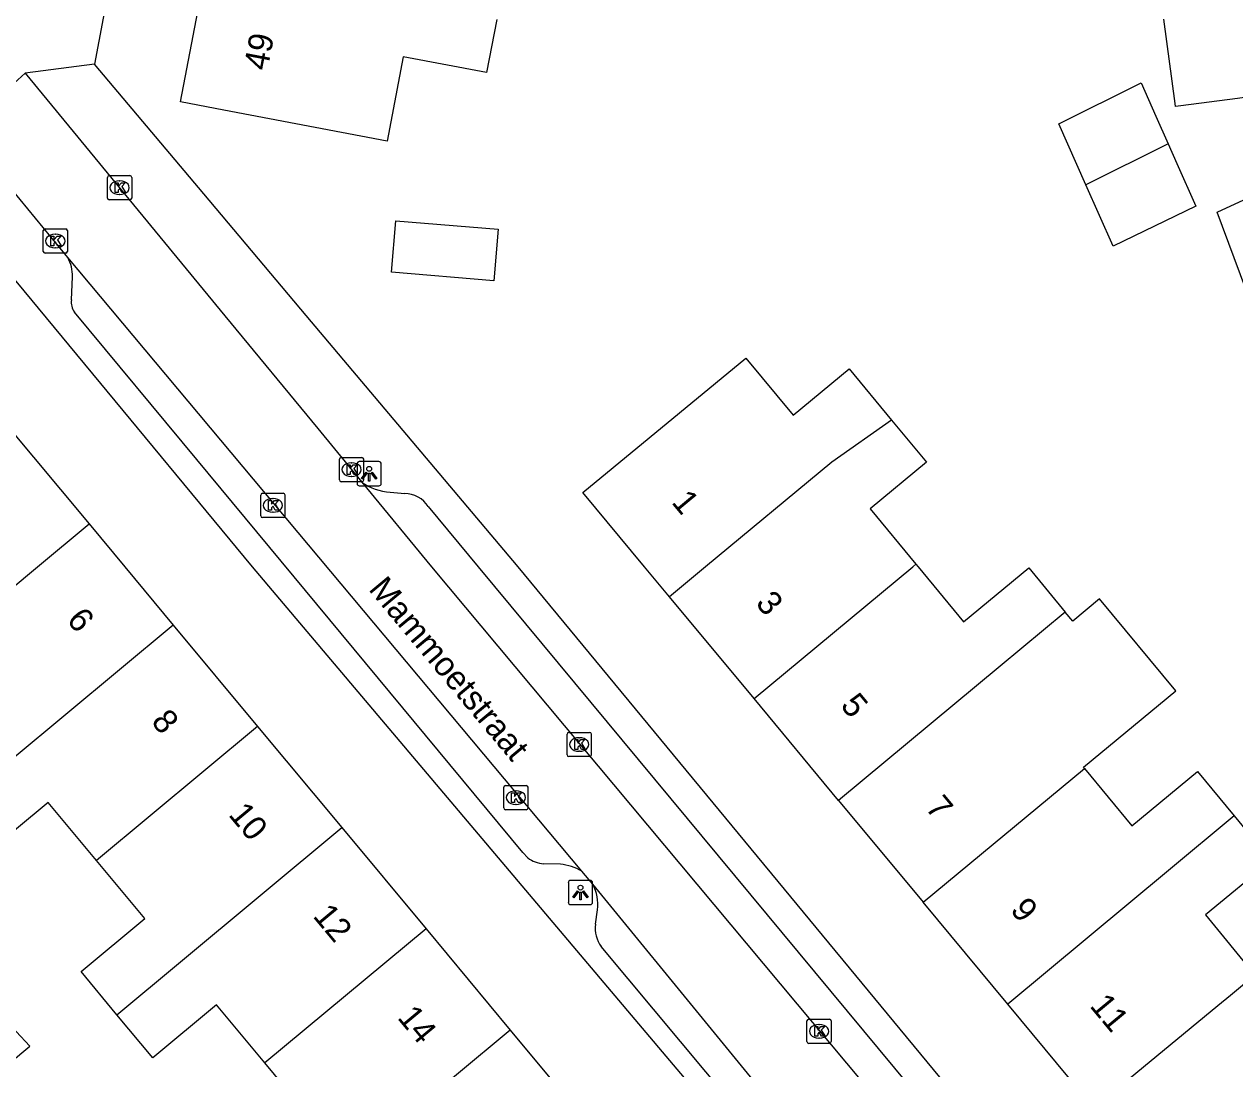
# Model space of a CAD drawing. Extents: x 163150 to 163546, y 380933 to 381635.
# Drawn here: x 163434.69 to 163484.57, y 380979.31 to 381022.35 of the extents above; entities that cross this region are included whole.
import ezdxf

# ---------------------------------------------------------------- set-up
doc = ezdxf.new("R2010")
doc.units = 0
for name, color, linetype in [('IMGEO_Kolk', 7, 'Continuous'), ('IMGEO_Lichtpunt', 7, 'Continuous'), ('IMGEO_Openbare_ruimte_label', 7, 'Continuous'), ('IMGEO_Pand', 7, 'Continuous'), ('IMGEO_Pand_nummerreeks', 7, 'Continuous'), ('IMGEO_Rijbaan_lokaal_open', 7, 'Continuous'), ('IMGEO_Voetpad_open', 7, 'Continuous')]:
    doc.layers.add(name, color=color, linetype=linetype)

msp = doc.modelspace()

# ---------------------------------------------------------------- linework, layer by layer
at = {"layer": 'IMGEO_Kolk'}
for p, q in [((163438.118, 381015.193), (163438.118, 381016.045)), ((163438.193, 381016.119), (163439.045, 381016.119)), ((163438.606, 381015.899), (163438.631, 381015.899)), ((163439.119, 381016.045), (163439.119, 381015.193)), ((163438.629, 381015.339), (163438.604, 381015.339)), ((163439.045, 381015.119), (163438.193, 381015.119)), ((163435.473, 381012.996), (163435.473, 381013.848)), ((163435.548, 381013.922), (163436.4, 381013.922)), ((163436.474, 381013.848), (163436.474, 381012.996)), ((163435.961, 381013.702), (163435.986, 381013.702)), ((163436.4, 381012.922), (163435.548, 381012.922)), ((163435.984, 381013.142), (163435.959, 381013.142)), ((163447.675, 381003.575), (163447.675, 381004.427)), ((163447.75, 381004.501), (163448.602, 381004.501)), ((163448.676, 381004.427), (163448.676, 381003.575)), ((163448.163, 381004.281), (163448.188, 381004.281)), ((163448.602, 381003.501), (163447.75, 381003.501)), ((163448.186, 381003.721), (163448.161, 381003.721)), ((163444.434, 381002.1), (163444.434, 381002.952)), ((163444.509, 381003.026), (163445.361, 381003.026)), ((163445.435, 381002.952), (163445.435, 381002.1)), ((163444.922, 381002.806), (163444.947, 381002.806)), ((163445.361, 381002.026), (163444.509, 381002.026)), ((163444.945, 381002.246), (163444.92, 381002.246)), ((163457.055, 380992.249), (163457.055, 380993.101)), ((163457.13, 380993.175), (163457.982, 380993.175)), ((163457.543, 380992.955), (163457.568, 380992.955)), ((163458.056, 380993.101), (163458.056, 380992.249)), ((163457.566, 380992.395), (163457.541, 380992.395)), ((163457.982, 380992.175), (163457.13, 380992.175)), ((163454.446, 380990.061), (163454.446, 380990.913)), ((163454.521, 380990.987), (163455.373, 380990.987)), ((163455.447, 380990.913), (163455.447, 380990.061)), ((163454.934, 380990.767), (163454.959, 380990.767)), ((163455.373, 380989.987), (163454.521, 380989.987)), ((163454.957, 380990.207), (163454.932, 380990.207)), ((163466.94, 380980.432), (163466.94, 380981.284)), ((163467.015, 380981.358), (163467.867, 380981.358)), ((163467.428, 380981.138), (163467.453, 380981.138)), ((163467.941, 380981.284), (163467.941, 380980.432)), ((163467.451, 380980.578), (163467.426, 380980.578)), ((163467.867, 380980.358), (163467.015, 380980.358))]:
    msp.add_line(p, q, dxfattribs=at)
for points in [[(163438.118, 381015.193), (163438.118, 381016.045)], [(163438.193, 381016.119), (163439.045, 381016.119)], [(163438.439, 381015.819), (163438.562, 381015.819), (163438.562, 381015.668), (163438.692, 381015.819), (163438.856, 381015.819), (163438.71, 381015.668), (163438.863, 381015.419), (163438.711, 381015.419), (163438.626, 381015.583), (163438.562, 381015.516), (163438.562, 381015.419), (163438.439, 381015.419), (163438.439, 381015.819)], [(163439.119, 381016.045), (163439.119, 381015.193)], [(163439.045, 381015.119), (163438.193, 381015.119)], [(163435.473, 381012.996), (163435.473, 381013.848)], [(163435.548, 381013.922), (163436.4, 381013.922)], [(163436.474, 381013.848), (163436.474, 381012.996)], [(163435.794, 381013.622), (163435.917, 381013.622), (163435.917, 381013.471), (163436.047, 381013.622), (163436.211, 381013.622), (163436.065, 381013.471), (163436.218, 381013.222), (163436.066, 381013.222), (163435.981, 381013.386), (163435.917, 381013.319), (163435.917, 381013.222), (163435.794, 381013.222), (163435.794, 381013.622)], [(163436.4, 381012.922), (163435.548, 381012.922)], [(163447.675, 381003.575), (163447.675, 381004.427)], [(163447.75, 381004.501), (163448.602, 381004.501)], [(163448.676, 381004.427), (163448.676, 381003.575)], [(163447.996, 381004.201), (163448.119, 381004.201), (163448.119, 381004.05), (163448.249, 381004.201), (163448.413, 381004.201), (163448.267, 381004.05), (163448.42, 381003.801), (163448.268, 381003.801), (163448.183, 381003.965), (163448.119, 381003.898), (163448.119, 381003.801), (163447.996, 381003.801), (163447.996, 381004.201)], [(163448.602, 381003.501), (163447.75, 381003.501)], [(163444.434, 381002.1), (163444.434, 381002.952)], [(163444.509, 381003.026), (163445.361, 381003.026)], [(163445.435, 381002.952), (163445.435, 381002.1)], [(163444.755, 381002.726), (163444.878, 381002.726), (163444.878, 381002.575), (163445.008, 381002.726), (163445.172, 381002.726), (163445.026, 381002.575), (163445.179, 381002.326), (163445.027, 381002.326), (163444.942, 381002.49), (163444.878, 381002.423), (163444.878, 381002.326), (163444.755, 381002.326), (163444.755, 381002.726)], [(163445.361, 381002.026), (163444.509, 381002.026)], [(163457.055, 380992.249), (163457.055, 380993.101)], [(163457.13, 380993.175), (163457.982, 380993.175)], [(163457.376, 380992.875), (163457.499, 380992.875), (163457.499, 380992.724), (163457.629, 380992.875), (163457.793, 380992.875), (163457.647, 380992.724), (163457.8, 380992.475), (163457.648, 380992.475), (163457.563, 380992.639), (163457.499, 380992.572), (163457.499, 380992.475), (163457.376, 380992.475), (163457.376, 380992.875)], [(163458.056, 380993.101), (163458.056, 380992.249)], [(163457.982, 380992.175), (163457.13, 380992.175)], [(163454.446, 380990.061), (163454.446, 380990.913)], [(163454.521, 380990.987), (163455.373, 380990.987)], [(163455.447, 380990.913), (163455.447, 380990.061)], [(163454.767, 380990.687), (163454.89, 380990.687), (163454.89, 380990.536), (163455.02, 380990.687), (163455.184, 380990.687), (163455.038, 380990.536), (163455.191, 380990.287), (163455.039, 380990.287), (163454.954, 380990.451), (163454.89, 380990.384), (163454.89, 380990.287), (163454.767, 380990.287), (163454.767, 380990.687)], [(163455.373, 380989.987), (163454.521, 380989.987)], [(163466.94, 380980.432), (163466.94, 380981.284)], [(163467.015, 380981.358), (163467.867, 380981.358)], [(163467.261, 380981.058), (163467.384, 380981.058), (163467.384, 380980.907), (163467.514, 380981.058), (163467.678, 380981.058), (163467.532, 380980.907), (163467.685, 380980.658), (163467.533, 380980.658), (163467.448, 380980.822), (163467.384, 380980.755), (163467.384, 380980.658), (163467.261, 380980.658), (163467.261, 380981.058)], [(163467.941, 380981.284), (163467.941, 380980.432)], [(163467.867, 380980.358), (163467.015, 380980.358)]]:
    msp.add_lwpolyline(points, dxfattribs=at)
for centre, start, end in [((163438.195, 381016.043), 91.552, 178.448), ((163438.195, 381016.043), 91.552, 178.448), ((163439.043, 381016.043), 1.552, 88.448), ((163439.043, 381016.043), 1.552, 88.448), ((163438.195, 381015.195), 181.552, 268.448), ((163438.195, 381015.195), 181.552, 268.448), ((163439.043, 381015.195), 271.552, 358.448), ((163439.043, 381015.195), 271.552, 358.448), ((163435.55, 381013.846), 91.552, 178.448), ((163435.55, 381013.846), 91.552, 178.448), ((163436.398, 381013.846), 1.552, 88.448), ((163436.398, 381013.846), 1.552, 88.448), ((163435.55, 381012.998), 181.552, 268.448), ((163435.55, 381012.998), 181.552, 268.448), ((163436.398, 381012.998), 271.552, 358.448), ((163436.398, 381012.998), 271.552, 358.448), ((163447.752, 381004.425), 91.552, 178.448), ((163447.752, 381004.425), 91.552, 178.448), ((163448.6, 381004.425), 1.552, 88.448), ((163448.6, 381004.425), 1.552, 88.448), ((163447.752, 381003.577), 181.552, 268.448), ((163447.752, 381003.577), 181.552, 268.448), ((163448.6, 381003.577), 271.552, 358.448), ((163448.6, 381003.577), 271.552, 358.448), ((163444.511, 381002.95), 91.552, 178.448), ((163444.511, 381002.95), 91.552, 178.448), ((163445.359, 381002.95), 1.552, 88.448), ((163445.359, 381002.95), 1.552, 88.448), ((163444.511, 381002.102), 181.552, 268.448), ((163444.511, 381002.102), 181.552, 268.448), ((163445.359, 381002.102), 271.552, 358.448), ((163445.359, 381002.102), 271.552, 358.448), ((163457.132, 380993.099), 91.552, 178.448), ((163457.132, 380993.099), 91.552, 178.448), ((163457.98, 380993.099), 1.552, 88.448), ((163457.98, 380993.099), 1.552, 88.448), ((163457.132, 380992.251), 181.552, 268.448), ((163457.132, 380992.251), 181.552, 268.448), ((163457.98, 380992.251), 271.552, 358.448), ((163457.98, 380992.251), 271.552, 358.448), ((163454.523, 380990.911), 91.552, 178.448), ((163454.523, 380990.911), 91.552, 178.448), ((163455.371, 380990.911), 1.552, 88.448), ((163455.371, 380990.911), 1.552, 88.448), ((163454.523, 380990.063), 181.552, 268.448), ((163454.523, 380990.063), 181.552, 268.448), ((163455.371, 380990.063), 271.552, 358.448), ((163455.371, 380990.063), 271.552, 358.448), ((163467.017, 380981.282), 91.552, 178.448), ((163467.017, 380981.282), 91.552, 178.448), ((163467.865, 380981.282), 1.552, 88.448), ((163467.865, 380981.282), 1.552, 88.448), ((163467.017, 380980.434), 181.552, 268.448), ((163467.017, 380980.434), 181.552, 268.448), ((163467.865, 380980.434), 271.552, 358.448), ((163467.865, 380980.434), 271.552, 358.448)]:
    msp.add_arc(centre, 0.0765, start, end, dxfattribs=at)
for centre, major_axis, ratio, start_param, end_param in [((163438.605, 381015.619), (-0.387, 0.002), 0.722429, 4.712389, 7.853982), ((163438.63, 381015.619), (-0.39, 0.002), 0.717154, 1.570796, 4.712389), ((163435.96, 381013.422), (-0.387, 0.002), 0.722429, 4.712389, 7.853982), ((163435.985, 381013.422), (-0.39, 0.002), 0.717154, 1.570796, 4.712389), ((163448.162, 381004.001), (-0.387, 0.002), 0.722429, 4.712389, 7.853982), ((163448.187, 381004.001), (-0.39, 0.002), 0.717154, 1.570796, 4.712389), ((163444.921, 381002.526), (-0.387, 0.002), 0.722429, 4.712389, 7.853982), ((163444.946, 381002.526), (-0.39, 0.002), 0.717154, 1.570796, 4.712389), ((163457.542, 380992.675), (-0.387, 0.002), 0.722429, 4.712389, 7.853982), ((163457.567, 380992.675), (-0.39, 0.002), 0.717154, 1.570796, 4.712389), ((163454.933, 380990.487), (-0.387, 0.002), 0.722429, 4.712389, 7.853982), ((163454.958, 380990.487), (-0.39, 0.002), 0.717154, 1.570796, 4.712389), ((163467.427, 380980.858), (-0.387, 0.002), 0.722429, 4.712389, 7.853982), ((163467.452, 380980.858), (-0.39, 0.002), 0.717154, 1.570796, 4.712389)]:
    msp.add_ellipse(centre, major_axis=major_axis, ratio=ratio, start_param=start_param, end_param=end_param, dxfattribs=at)
at = {"layer": 'IMGEO_Lichtpunt'}
for p, q in [((163449.305, 381004.332), (163448.497, 381004.332)), ((163449.305, 381004.332), (163448.497, 381004.332)), ((163448.403, 381004.237), (163448.403, 381003.43)), ((163448.403, 381004.237), (163448.403, 381003.43)), ((163449.399, 381003.43), (163449.399, 381004.237)), ((163449.399, 381003.43), (163449.399, 381004.237)), ((163448.497, 381003.336), (163449.305, 381003.336)), ((163448.497, 381003.336), (163449.305, 381003.336)), ((163457.109, 380986.981), (163457.109, 380986.174)), ((163457.109, 380986.981), (163457.109, 380986.174)), ((163458.011, 380987.076), (163457.203, 380987.076)), ((163458.011, 380987.076), (163457.203, 380987.076)), ((163458.105, 380986.174), (163458.105, 380986.981)), ((163458.105, 380986.174), (163458.105, 380986.981)), ((163457.203, 380986.08), (163458.011, 380986.08)), ((163457.203, 380986.08), (163458.011, 380986.08))]:
    msp.add_line(p, q, dxfattribs=at)
for points in [[(163448.777, 381003.901), (163448.816, 381003.873), (163448.628, 381003.611), (163448.59, 381003.638), (163448.777, 381003.901)], [(163448.879, 381003.853), (163448.926, 381003.853), (163448.926, 381003.531), (163448.879, 381003.531), (163448.879, 381003.853)], [(163448.989, 381003.873), (163449.027, 381003.9), (163449.214, 381003.638), (163449.175, 381003.61), (163448.989, 381003.873)], [(163457.483, 380986.645), (163457.522, 380986.617), (163457.334, 380986.355), (163457.296, 380986.382), (163457.483, 380986.645)], [(163457.585, 380986.597), (163457.632, 380986.597), (163457.632, 380986.275), (163457.585, 380986.275), (163457.585, 380986.597)], [(163457.695, 380986.617), (163457.733, 380986.644), (163457.92, 380986.382), (163457.881, 380986.354), (163457.695, 380986.617)]]:
    msp.add_lwpolyline(points, dxfattribs=at)
for centre in [(163448.902, 381004.035), (163457.608, 380986.779)]:
    msp.add_circle(centre, 0.0994, dxfattribs=at)
for centre, start, end in [((163448.497, 381004.237), 90, 180), ((163448.497, 381004.237), 90, 180), ((163449.305, 381004.237), 0, 90), ((163449.305, 381004.237), 0, 90), ((163448.497, 381003.43), 180, 270), ((163448.497, 381003.43), 180, 270), ((163449.305, 381003.43), 270, 0), ((163449.305, 381003.43), 270, 360), ((163457.203, 380986.981), 90, 180), ((163457.203, 380986.981), 90, 180), ((163458.011, 380986.981), 0, 90), ((163458.011, 380986.981), 0, 90), ((163457.203, 380986.174), 180, 270), ((163457.203, 380986.174), 180, 270), ((163458.011, 380986.174), 270, 0), ((163458.011, 380986.174), 270, 360)]:
    msp.add_arc(centre, 0.0946, start, end, dxfattribs=at)
at = {"layer": 'IMGEO_Pand'}
for points in [[(163454.161, 381022.555), (163453.744, 381020.362), (163450.31, 381021.016), (163449.647, 381017.536), (163442.912, 381018.819), (163441.133, 381019.158), (163442.172, 381024.615)], [(163485.255, 381019.37), (163484.681, 381019.295), (163482.342, 381018.99), (163482.127, 381018.962), (163482.111, 381019.085), (163481.639, 381022.556)], [(163478.437, 381015.733), (163477.318, 381018.254), (163480.704, 381019.942), (163481.317, 381018.56), (163481.823, 381017.421)], [(163481.823, 381017.421), (163482.182, 381016.612), (163482.961, 381014.858), (163479.556, 381013.213), (163478.437, 381015.733)], [(163481.823, 381017.421), (163478.437, 381015.733)], [(163485.019, 381011.437), (163483.839, 381014.613), (163486.545, 381015.861)], [(163454.038, 381011.787), (163449.827, 381012.14), (163450.004, 381014.258), (163454.215, 381013.905), (163454.038, 381011.787)], [(163461.277, 380998.765), (163460.251, 381000), (163457.711, 381003.059), (163464.426, 381008.598), (163466.369, 381006.243), (163468.677, 381008.159), (163470.427, 381006.038)], [(163433.893, 381005.936), (163437.364, 381001.765)], [(163470.427, 381006.038), (163467.96, 381004.314), (163462.764, 381000), (163461.277, 380998.765)], [(163470.427, 381006.038), (163471.859, 381004.302), (163469.551, 381002.386), (163471.431, 381000.107)], [(163430.721, 380996.239), (163435.243, 381000), (163437.364, 381001.765)], [(163437.364, 381001.765), (163438.832, 381000), (163440.834, 380997.593)], [(163464.761, 380994.568), (163471.302, 381000), (163471.431, 381000.107)], [(163471.431, 381000.107), (163471.519, 381000), (163473.387, 380997.736), (163476.077, 380999.956), (163477.585, 380998.128)], [(163464.761, 380994.568), (163461.277, 380998.765)], [(163478.371, 380991.693), (163478.337, 380991.735), (163482.137, 380994.89), (163478.995, 380998.675), (163477.89, 380997.758), (163477.585, 380998.128)], [(163477.585, 380998.128), (163474.901, 380995.9), (163468.244, 380990.373)], [(163440.834, 380997.593), (163434.193, 380992.067), (163431.571, 380989.886)], [(163440.834, 380997.593), (163444.305, 380993.421)], [(163468.244, 380990.373), (163464.761, 380994.568)], [(163444.305, 380993.421), (163437.663, 380987.896)], [(163444.305, 380993.421), (163447.775, 380989.25)], [(163471.728, 380986.177), (163478.371, 380991.693)], [(163478.371, 380991.693), (163480.326, 380989.323), (163483.038, 380991.56), (163484.546, 380989.732)], [(163468.244, 380990.373), (163471.728, 380986.177)], [(163437.663, 380987.896), (163435.671, 380990.291), (163433.049, 380988.109), (163431.571, 380989.886)], [(163484.546, 380989.732), (163486.067, 380987.888), (163483.355, 380985.651), (163485.4, 380983.172), (163484.386, 380982.336), (163483.867, 380981.908), (163479.391, 380978.216), (163478.766, 380977.7), (163475.211, 380981.981)], [(163484.546, 380989.732), (163481.841, 380987.486), (163475.211, 380981.981)], [(163438.513, 380981.543), (163441.134, 380983.724), (163447.775, 380989.25)], [(163447.775, 380989.25), (163451.246, 380985.078)], [(163438.513, 380981.543), (163437.035, 380983.319), (163439.656, 380985.5), (163437.663, 380987.896)], [(163475.211, 380981.981), (163471.728, 380986.177)], [(163451.246, 380985.078), (163444.605, 380979.553)], [(163451.246, 380985.078), (163454.717, 380980.906)], [(163432.558, 380978.28), (163434.926, 380980.25), (163432.095, 380983.264)], [(163444.605, 380979.553), (163442.612, 380981.948), (163439.991, 380979.767), (163438.513, 380981.543)], [(163454.717, 380980.906), (163448.076, 380975.381), (163445.455, 380973.2)], [(163454.717, 380980.906), (163458.188, 380976.735)], [(163445.455, 380973.2), (163443.977, 380974.976), (163446.598, 380977.157), (163444.605, 380979.553)]]:
    msp.add_lwpolyline(points, dxfattribs=at)
at = {"layer": 'IMGEO_Rijbaan_lokaal_open'}
for points in [[(163432.143, 381018.005), (163434.736, 381020.337)], [(163434.736, 381020.337), (163442.958, 381010.342), (163446.783, 381005.693), (163448.598, 381003.486)], [(163436.489, 381012.744), (163435.783, 381013.597), (163432.926, 381017.057), (163432.143, 381018.005)], [(163457.662, 380987.457), (163436.489, 381012.744)], [(163448.598, 381003.486), (163451.466, 381000), (163471.302, 380976.274)], [(163458.125, 380986.915), (163457.662, 380987.457)], [(163468.143, 380974.673), (163458.125, 380986.915)]]:
    msp.add_lwpolyline(points, dxfattribs=at)
at = {"layer": 'IMGEO_Voetpad_open'}
for points in [[(163449.567, 381084.29), (163437.58, 381020.705)], [(163437.58, 381020.705), (163434.736, 381020.337)], [(163500.852, 380970.985), (163500, 380970.878), (163481.073, 380968.493), (163480.619, 380969.042), (163477.178, 380973.206), (163475.613, 380975.099), (163455.037, 381000), (163446.308, 381010.353), (163442.086, 381015.361), (163437.58, 381020.705)], [(163430.255, 381016.703), (163444.089, 381000), (163465.785, 380974.327)], [(163436.634, 381011.001), (163436.683, 381011.946)], [(163455.441, 380988.008), (163455.241, 380988.23), (163441.802, 381004.415), (163436.767, 381010.488)], [(163449.77, 381003.073), (163450.366, 381003.014)], [(163451.336, 381002.479), (163453.398, 381000), (163471.219, 380978.526)], [(163456.782, 380987.744), (163456.088, 380987.765)], [(163458.222, 380985.27), (163458.316, 380985.869)], [(163466.037, 380975.28), (163458.458, 380984.351)]]:
    msp.add_lwpolyline(points, dxfattribs=at)
for centre, radius, start, end in [((163435.012, 381011.962), 1.671, 359.4365, 27.8914), ((163437.297, 381010.899), 0.671, 171.2606, 217.8083), ((163449.895, 381005.297), 2.228, 234.3945, 266.7817), ((163450.354, 381001.846), 1.168, 32.8239, 89.4185), ((163456.174, 380988.976), 1.214, 232.8776, 265.9521), ((163456.508, 380985.412), 2.348, 60.5708, 83.3031), ((163456.332, 380986.047), 1.992, 354.8659, 25.8306), ((163459.539, 380985.118), 1.325, 173.4289, 215.3759)]:
    msp.add_arc(centre, radius, start, end, dxfattribs=at)

# ---------------------------------------------------------------- texts
at = {"layer": 'IMGEO_Openbare_ruimte_label'}
msp.add_text('Mammoetstraat', height=1, rotation=309.8496, dxfattribs=at).set_placement((163448.845, 380999.061))
at = {"layer": 'IMGEO_Pand_nummerreeks'}
for s, rotation, p in [('49', 79.2164, (163444.711, 381020.411)), ('1', 309.7041, (163461.33, 381002.646)), ('3', 309.7008, (163464.789, 380998.48)), ('6', 309.759, (163436.405, 380997.787)), ('5', 309.7008, (163468.287, 380994.267)), ('8', 309.759, (163439.889, 380993.6)), ('7', 309.7, (163471.784, 380990.054)), ('10', 309.759, (163443.075, 380989.772)), ('12', 309.759, (163446.551, 380985.594)), ('9', 309.7008, (163475.283, 380985.841)), ('11', 309.7008, (163478.558, 380981.894)), ('14', 309.759, (163450.033, 380981.409))]:
    msp.add_text(s, height=1, rotation=rotation, dxfattribs=at).set_placement(p)

doc.saveas('drawing.dxf')
